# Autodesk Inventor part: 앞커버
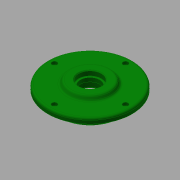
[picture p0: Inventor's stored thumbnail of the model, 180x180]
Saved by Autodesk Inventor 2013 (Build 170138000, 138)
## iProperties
Created: 2016-11
Part Number: 앞커버
Material: 일반
Document SubType Name: Modeling
Designer: mduedu
Density: 1 g/cm^3
Mass: 188.69 g
Surface Area: 365.029 cm^2
Volume: 188.69 cm^3
Author: mduedu
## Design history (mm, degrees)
sketch "스케치1"
  geometry: L1 (28.5, -17.5)-(28.5, -30); L2 (28.5, -30)-(22.5, -33.464); L3 (22.5, -33.464)-(22.5, -65); L4 (22.5, -65)-(14.5, -65); L5 (14.5, -65)-(14.5, -47.5); L6 (14.5, -47.5)-(0, -47.5); L7 (0, -47.5)-(0, -23.5); L8 (0, 0)-(28.5, 0); L9 (14.5, -23.5)-(14.5, -15); L10 (14.5, -15)-(20.5, -15); L11 (20.5, -15)-(20.5, -17.5); L12 (0, -23.5)-(14.5, -23.5); L13 (20.5, -17.5)-(28.5, -17.5)
  constraints: 26 end point, 8 parallel, 3 perpendicular, 2 horizontal, 2 vertical alignment, 1 collinear
  dimensions: "d0" = 14.5 distance of L5.end L6.end; "d2" = 8 distance of L3.end L4.end; "d3" = 6 distance between parallel lines of L1 L3; "d4" = 120 deg angle of L3 L2; "d5" = 8 distance of L11.end L1.start; "d6" = 60 diameter of L1.end L8; "d7" = 30 diameter of L10 L8; "d8" = 47 diameter of L12 L8; "d9" = 35 diameter of L13 L8; "d10" = 95 diameter of L6 L8; "d11" = 130 diameter of L4 L8
revolve "회전1" sketch "스케치1" stored, may be unused: angle "d12" = 90 deg
fillet "모깎기1" dims "d13" = 0.5
fillet "모깎기2" dims "d14" = 3
chamfer "모따기1" distance "d15" = 1; stored, may be unused: second distance "d16" = 2, angle "d17" = 45 deg
fillet "모깎기3" dims "d18" = 0.3
sketch "스케치2" dims "d19" = 110
  geometry: 6 further points
  constraints: 2 vertical alignment, 1 coincident, 7 other
  dimensions: "d22" = 360 deg dimension on point (0, 0) point (0, 55) (derived)
sketch "스케치3"
  geometry: 4 further points
  constraints: 4 other
hole "구멍1" sketch "스케치3" at (0, 55), (-55, 0), (55, 0), (0, -55) diameter "d24" = 4.5; stored, may be unused: countersink angle "d28" = 90 deg, drill point angle "d30" = 0 deg; dims "d25" = 6, "d26" = 8, "d27" = 4.6, "d29" = 8
node "솔리드1"
